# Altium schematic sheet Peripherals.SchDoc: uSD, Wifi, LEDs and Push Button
size A4; Date: 29-OCT-2015; Author: A.B; CompanyName: STMicroelectronics; Organization: MCD/TOOLS/GNB; Address1: 12, Rue Jules HOROWITZ; Address2: 38019 Grenoble; Address3: FRANCE; DocumentNumber: MB1225; Revision: B-01; SheetNumber: 12; SheetTotal: 12; Project: STM32F769I-DISCO
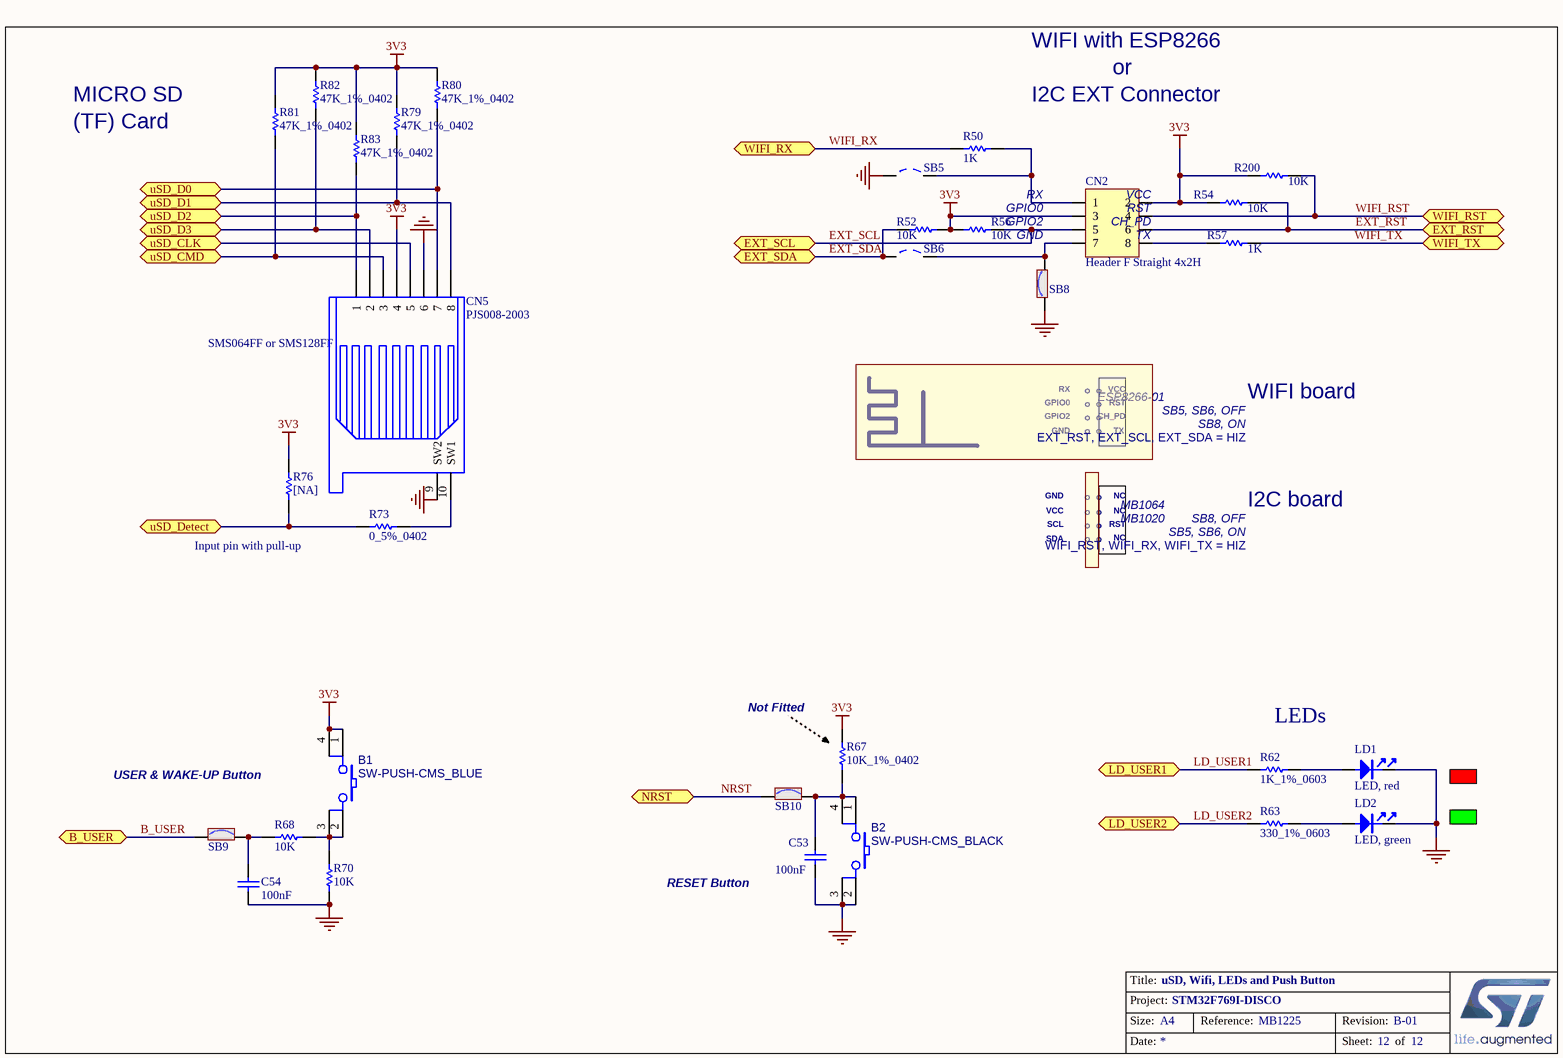
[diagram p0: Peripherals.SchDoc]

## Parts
B1  SW-PUSH-CMS_BLUE  [PB10]
B2  SW-PUSH-CMS_BLACK  [PB10]
C53  100nF  [0402C]
C54  100nF  [0402C]
CN2  Header F Straight 4x2H  [HDR_2X4_2R54]
CN5  PJS008-2003  [MSD_PJS008_]
LD1  LED, red  [0603D]
LD2  LED, green  [0603D]
R50  1K  [0402R]
R52  10K  [0402R]
R54  10K  [0402R]
R56  10K  [0402R]
R57  1K  [0402R]
R62  1K_1%_0603  [0603R]
R63  330_1%_0603  [0603R]
R67  10K_1%_0402  [0402R]
R68  10K  [0402R]
R70  10K  [0402R]
R73  0_5%_0402  [0402R]
R76  [NA]  [0402R]
R79  47K_1%_0402  [0402R]
R80  47K_1%_0402  [0402R]
R81  47K_1%_0402  [0402R]
R82  47K_1%_0402  [0402R]
R83  47K_1%_0402  [0402R]
R200  10K  [0402R]
SB5  Solder Bridge OFF  [JP2_SMD]  (value not drawn)
SB6  Solder Bridge OFF  [JP2_SMD]  (value not drawn)
SB8  Solder Bridge ON  [JP2_SMD]  (value not drawn)
SB9  Solder Bridge ON  [JP2_SMD]  (value not drawn)
SB10  Solder Bridge ON  [JP2_SMD]  (value not drawn)

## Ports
B_USER, EXT_RST, EXT_SCL, EXT_SDA, LD_USER1, LD_USER2, NRST, uSD_CLK, uSD_CMD, uSD_D0, uSD_D1, uSD_D2, uSD_D3, uSD_Detect, WIFI_RST, WIFI_RX, WIFI_TX

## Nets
3V3: B1.1 B1.4 CN2.2 CN2.3 CN5.4 R52.2 R54.1 R56.1 R67.2 R76.2 R79.2 R80.2 R81.2 R82.2 R83.2 R200.1
GND: B2.2 B2.3 C53.1 C54.1 CN5.6 CN5.9(SW2) LD1.2 LD2.2 R70.1 SB5.1 SB8.1
B_USER: SB9.1 ; port B_USER
EXT_RST: CN2.6 R54.2 ; port EXT_RST
EXT_SCL: CN2.5 R56.2 ; port EXT_SCL
EXT_SDA: R52.1 SB6.1 ; port EXT_SDA
LD_USER1: R62.1 ; port LD_USER1
LD_USER2: R63.1 ; port LD_USER2
NRST: SB10.1 ; port NRST
uSD_CLK: CN5.5 ; port uSD_CLK
uSD_CMD: CN5.3 R81.1 ; port uSD_CMD
uSD_D0: CN5.7 R80.1 ; port uSD_D0
uSD_D1: CN5.8 R79.1 ; port uSD_D1
uSD_D2: CN5.1 R83.1 ; port uSD_D2
uSD_D3: CN5.2 R82.1 ; port uSD_D3
uSD_Detect: R73.1 R76.1 ; port uSD_Detect
WIFI_RST: CN2.4 R200.2 ; port WIFI_RST
WIFI_RX: R50.1 ; port WIFI_RX
WIFI_TX: R57.2 ; port WIFI_TX
NetB1_2: B1.2 B1.3 R68.2 R70.2
NetB2_1: B2.1 B2.4 C53.2 R67.1 SB10.2
NetC54_2: C54.2 R68.1 SB9.2
NetCN2_1: CN2.1 R50.2 SB5.2
NetCN2_7: CN2.7 SB6.2 SB8.2
NetCN2_8: CN2.8 R57.1
NetCN5_10: CN5.10(SW1) R73.2
NetLD1_1: LD1.1 R62.2
NetLD2_1: LD2.1 R63.2

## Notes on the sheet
- WIFI with ESP8266
- MICRO SD
- (TF) Card
- I2C EXT Connector
- or
- (near CN2) RX
- (near CN2) VCC
- GND
- (near CN2) GPIO2
- (near CN2) GPIO0
- (near CN2) CH_PD
- (near CN2) RST
- (near CN2) TX
- (near CN5) SMS064FF or SMS128FF
- GPIO0
- RX
- ° °
- VCC
- RST
- ESP8266-01
- WIFI board
- GPIO2
- TX
- CH_PD
- SB5, SB6, OFF
- SB8, ON
- EXT_RST, EXT_SCL, EXT_SDA = HIZ
- SCL
- SDA
- NC
- MB1064
- MB1020
- I2C board
- SB8, OFF
- SB5, SB6, ON
- Input pin with pull-up
- WIFI_RST, WIFI_RX, WIFI_TX = HIZ
- (near R67) Not Fitted
- LEDs
- USER & WAKE-UP Button
- RESET Button

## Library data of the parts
B1 = SW-PUSH-CMS_BLUE: Non-Open Push-Button 0.1A 24V; Manuf_2: FARNELL; Manuf_Part_2: 535-930; Manuf_1: wealthmetal; Manuf_Part_1: TD0341X-G01-BLU; Ref St: 9180120; Description: Non-Open Push Button,Blue 0.1A 24V,Square head,6*6,SMT,180Degree,TD-0341X-GO1,wealthmetal; SMEE_FP: BP1CMS; Provided: Sub Co
B2 = SW-PUSH-CMS_BLACK: Non-Open Push-Button 0.1A 24V; Manuf_2: FARNELL; Manuf_Part_2: 535-930; Manuf_1: wealthmetal; Manuf_Part_1: TD0341X-G01-BLA; Ref St: 9180120; Description: Non-Open Push Button,Black 0.1A 24V,Square head,6*6,SMT,180Degree,TD-0341X-GO1,wealthmetal; SMEE_FP: BP1CMS; SOFER_FP: BP10; Provided: Sub Co
C53 C54 = Cap_100nF_X7R_10%_0402: Capacitor,100nF,16V,X7R,10%,0402,YAGEO; Manuf_Part_1: CC0402KRX7R7BB104
CN2 = Header 4X2F: Header Female, 4-Pin, Dual row, Straight; Manuf_Part_1: BL 2-8G; Manuf_1: Fischer Electronik
CN5 = microSD-PJS008-2003: Memory Card Connectors MicroSD Card Conn Revrs Mnt Push-Push; Manuf_Part_1: PJS008-2003-1; Manuf_1: YAMAICHI
LD1 = LED_red: LED, red, 0603; Manuf_1: everlight; Manuf_Part_1: 19-213-R6C-AP1Q2B/3T; Description: LED,red,0603,19-213-R6C-AP1Q2B/3T,everlight; ECCN_US/EU: EAR99/NEC
LD2 = LED_green: LED, green, 0603; Manuf_1: everlight; Manuf_Part_1: 19-213SYGC/S530-E2/TR8; Description: LED,green,0603,19-213SYGC/S530-E2/TR8,everlight; ECCN_US/EU: EAR99/NEC
R50 R57 = Res_1K_1%_0402: Resistor,1K,0402,1%,YAGEO; Manuf_Part_1: RC0402FR-071KL
R52 R54 R56 R68 R70 R200 = Res_10K_1%_0402: Resistor,10K,0402,1%,YAGEO; Manuf_Part_1: RC0402FR-0710KL
R62 = Res_1K_1%_0603: Resistor,1K,0603,1%,YAGEO; Manuf_Part_1: RC0603FR-071KL
R63 = Res_330_1%_0603: Resistor,330,0603,1%,YAGEO; Manuf_Part_1: RC0603FR-07330RL; Manuf_Part_2: RT0603FRE07330RL; Value: 330
R67 = Res_10K_1%_0402: Resistor,10K,0402,1%,YAGEO; Manuf_Part_1: RC0402FR-0710KL; Fitted: NO
R73 = Res_0_5%_0402: Resistor,0,0402,5%,YAGEO; Manuf_Part_1: RC0402JR-070RL; Value: 0; Order: 2363467
R76 = Res_NA_0402: Resistor,[NA],0402; Fitted: NO
R79-R83 = Res_47K_1%_0402: Resistor,47K,0402,1%,YAGEO; Manuf_Part_1: RC0402FR-0747KL; Order: 9239430
SB5 SB6 = SB_OFF: Solder: NO
SB8-SB10 = SB_ON: Solder: YES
